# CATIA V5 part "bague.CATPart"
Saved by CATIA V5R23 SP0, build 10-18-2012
Part number: bague
Definition: bague
Source: made
Bounding box of the stored display mesh (mm): x -7 to 7, y -7 to 7, z -5 to 5
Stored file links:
  C:\wamp\www\COURS\CONCEPTION GMP1\TITRE 01-CATIA VOLUMIQUE\05--ACTIONNEUR DE VANNE\prof\CORRECTION\Assemblage\bague.CATPart
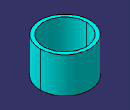
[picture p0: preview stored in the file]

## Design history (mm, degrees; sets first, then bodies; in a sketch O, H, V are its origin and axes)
Body1 "NONE" (main body)
  Solid1 "Manifold Solid #108": solid without history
